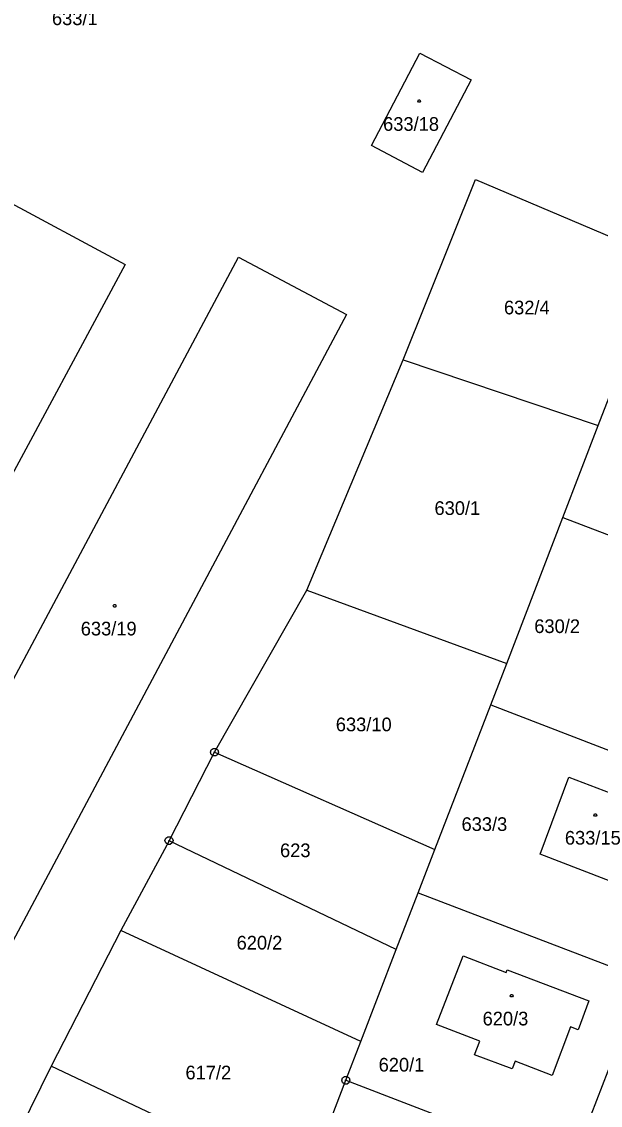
# Model space of a CAD drawing. Extents: x -759060 to -757386, y -1172273 to -1170948.
# Drawn here: x -758247.7 to -758175.7, y -1171430.9 to -1171296.1 of the extents above; entities that cross this region are included whole.
import ezdxf

# ---------------------------------------------------------------- set-up
doc = ezdxf.new("R2010")
doc.units = 0
for name, color, linetype in [('Vrstva 1', 7, 'Continuous'), ('Vrstva 12', 7, 'Continuous'), ('Vrstva 2', 7, 'Continuous'), ('Vrstva 5', 7, 'Continuous'), ('Vrstva 8', 7, 'Continuous')]:
    doc.layers.add(name, color=color, linetype=linetype)

msp = doc.modelspace()

# ---------------------------------------------------------------- linework, layer by layer
at = {"layer": 'Vrstva 1'}
for p, q in [((-758204.21, -1171311.5), (-758198.17, -1171299.99)), ((-758198.17, -1171299.99), (-758191.81, -1171303.33)), ((-758191.81, -1171303.33), (-758197.86, -1171314.86)), ((-758267.3, -1171308.84), (-758234.85, -1171326.27)), ((-758197.86, -1171314.86), (-758204.21, -1171311.5)), ((-758200.25, -1171338.13), (-758191.24, -1171315.72)), ((-758191.24, -1171315.72), (-758168.03, -1171325.59)), ((-758263.01, -1171404.59), (-758220.74, -1171325.36)), ((-758220.74, -1171325.36), (-758207.32, -1171332.5)), ((-758234.85, -1171326.27), (-758257.96, -1171369.23)), ((-758207.32, -1171332.5), (-758249.54, -1171411.77)), ((-758175.99, -1171346.32), (-758171.41, -1171334.41)), ((-758212.25, -1171366.8), (-758200.25, -1171338.13)), ((-758200.25, -1171338.13), (-758175.99, -1171346.32)), ((-758180.38, -1171357.75), (-758175.99, -1171346.32)), ((-758187.37, -1171375.93), (-758180.38, -1171357.75)), ((-758180.38, -1171357.75), (-758152.42, -1171368.5)), ((-758223.72, -1171386.96), (-758212.25, -1171366.8)), ((-758212.25, -1171366.8), (-758187.37, -1171375.93)), ((-758189.35, -1171381.08), (-758187.37, -1171375.93)), ((-758196.3, -1171399.06), (-758189.35, -1171381.08)), ((-758189.35, -1171381.08), (-758161.39, -1171391.83)), ((-758229.38, -1171397.96), (-758223.72, -1171386.96)), ((-758223.72, -1171386.96), (-758196.3, -1171399.06)), ((-758183.23, -1171399.64), (-758179.64, -1171390.04)), ((-758179.64, -1171390.04), (-758168.69, -1171394.27)), ((-758229.38, -1171397.96), (-758235.4, -1171409.14)), ((-758201.11, -1171411.49), (-758229.38, -1171397.96)), ((-758198.38, -1171404.43), (-758196.3, -1171399.06)), ((-758172.46, -1171403.81), (-758183.23, -1171399.64)), ((-758201.11, -1171411.49), (-758198.38, -1171404.43)), ((-758198.38, -1171404.43), (-758170.38, -1171415.15)), ((-758235.4, -1171409.14), (-758244.03, -1171426.01)), ((-758205.53, -1171422.96), (-758235.4, -1171409.14)), ((-758205.53, -1171422.96), (-758201.11, -1171411.49)), ((-758196.09, -1171420.83), (-758192.8, -1171412.3)), ((-758192.8, -1171412.3), (-758187.44, -1171414.37)), ((-758187.44, -1171414.37), (-758187.31, -1171414.03)), ((-758187.31, -1171414.03), (-758177.15, -1171417.9)), ((-758170.38, -1171415.15), (-758179.37, -1171438.48)), ((-758177.15, -1171417.9), (-758178.48, -1171421.47)), ((-758190.71, -1171422.89), (-758196.09, -1171420.83)), ((-758179.42, -1171421.11), (-758181.73, -1171427.19)), ((-758178.48, -1171421.47), (-758179.42, -1171421.11)), ((-758207.39, -1171427.77), (-758205.53, -1171422.96)), ((-758191.36, -1171424.58), (-758190.71, -1171422.89)), ((-758186.71, -1171426.34), (-758191.36, -1171424.58)), ((-758186.34, -1171425.38), (-758186.71, -1171426.34)), ((-758181.73, -1171427.19), (-758186.34, -1171425.38)), ((-758244.03, -1171426.01), (-758252.61, -1171443.29)), ((-758212.47, -1171440.95), (-758244.03, -1171426.01)), ((-758212.47, -1171440.95), (-758207.39, -1171427.77)), ((-758207.39, -1171427.77), (-758179.37, -1171438.48))]:
    msp.add_line(p, q, dxfattribs=at)
at = {"layer": 'Vrstva 12'}
for p, q in [((-758204.21, -1171311.5), (-758198.17, -1171299.99)), ((-758198.17, -1171299.99), (-758191.81, -1171303.33)), ((-758191.81, -1171303.33), (-758197.86, -1171314.86)), ((-758267.3, -1171308.84), (-758234.85, -1171326.27)), ((-758197.86, -1171314.86), (-758204.21, -1171311.5)), ((-758263.01, -1171404.59), (-758220.74, -1171325.36)), ((-758220.74, -1171325.36), (-758207.32, -1171332.5)), ((-758234.85, -1171326.27), (-758257.96, -1171369.23)), ((-758207.32, -1171332.5), (-758249.54, -1171411.77)), ((-758183.23, -1171399.64), (-758179.64, -1171390.04)), ((-758179.64, -1171390.04), (-758168.69, -1171394.27)), ((-758172.46, -1171403.81), (-758183.23, -1171399.64)), ((-758196.09, -1171420.83), (-758192.8, -1171412.3)), ((-758192.8, -1171412.3), (-758187.44, -1171414.37)), ((-758187.44, -1171414.37), (-758187.31, -1171414.03)), ((-758187.31, -1171414.03), (-758177.15, -1171417.9)), ((-758177.15, -1171417.9), (-758178.48, -1171421.47)), ((-758190.71, -1171422.89), (-758196.09, -1171420.83)), ((-758179.42, -1171421.11), (-758181.73, -1171427.19)), ((-758178.48, -1171421.47), (-758179.42, -1171421.11)), ((-758191.36, -1171424.58), (-758190.71, -1171422.89)), ((-758186.71, -1171426.34), (-758191.36, -1171424.58)), ((-758186.34, -1171425.38), (-758186.71, -1171426.34)), ((-758181.73, -1171427.19), (-758186.34, -1171425.38))]:
    msp.add_line(p, q, dxfattribs=at)
at = {"layer": 'Vrstva 5'}
for points in [[(-758198.17, -1171305.8), (-758198.08, -1171305.95), (-758198.17, -1171306.1), (-758198.35, -1171306.1), (-758198.44, -1171305.95), (-758198.35, -1171305.8)], [(-758236.07, -1171368.6), (-758235.98, -1171368.75), (-758236.07, -1171368.9), (-758236.25, -1171368.9), (-758236.34, -1171368.75), (-758236.25, -1171368.6)], [(-758176.26, -1171394.62), (-758176.17, -1171394.77), (-758176.26, -1171394.92), (-758176.44, -1171394.92), (-758176.53, -1171394.77), (-758176.44, -1171394.62)], [(-758186.67, -1171417.09), (-758186.58, -1171417.24), (-758186.67, -1171417.39), (-758186.85, -1171417.39), (-758186.94, -1171417.24), (-758186.85, -1171417.09)]]:
    msp.add_lwpolyline(points, close=True, dxfattribs=at)
at = {"layer": 'Vrstva 8'}
for p, q in [((-758223.84, -1171386.96), (-758223.6, -1171386.96)), ((-758229.5, -1171397.96), (-758229.26, -1171397.96)), ((-758207.51, -1171427.77), (-758207.27, -1171427.77))]:
    msp.add_line(p, q, dxfattribs=at)
for points in [[(-758223.57, -1171386.48), (-758223.32, -1171386.66), (-758223.22, -1171386.95), (-758223.32, -1171387.24), (-758223.57, -1171387.42), (-758223.88, -1171387.42), (-758224.13, -1171387.24), (-758224.23, -1171386.95), (-758224.13, -1171386.66), (-758223.88, -1171386.48)], [(-758229.23, -1171397.48), (-758228.98, -1171397.66), (-758228.88, -1171397.95), (-758228.98, -1171398.24), (-758229.23, -1171398.42), (-758229.54, -1171398.42), (-758229.79, -1171398.24), (-758229.89, -1171397.95), (-758229.79, -1171397.66), (-758229.54, -1171397.48)], [(-758207.24, -1171427.29), (-758206.99, -1171427.47), (-758206.89, -1171427.76), (-758206.99, -1171428.05), (-758207.24, -1171428.23), (-758207.55, -1171428.23), (-758207.8, -1171428.05), (-758207.9, -1171427.76), (-758207.8, -1171427.47), (-758207.55, -1171427.29)]]:
    msp.add_lwpolyline(points, close=True, dxfattribs=at)

# ---------------------------------------------------------------- texts
at = {"layer": 'Vrstva 2'}
for s, p in [('633/1', (-758243.949, -1171296.51)), ('633/18', (-758202.749, -1171309.66)), ('632/4', (-758187.714, -1171332.49)), ('630/1', (-758196.359, -1171357.44)), ('630/2', (-758183.941, -1171372.13)), ('633/19', (-758240.368, -1171372.43)), ('633/10', (-758208.635, -1171384.35)), ('633/3', (-758192.994, -1171396.75)), ('633/15', (-758180.135, -1171398.45)), ('623', (-758215.575, -1171400.01)), ('620/2', (-758220.977, -1171411.5)), ('620/3', (-758190.371, -1171420.94)), ('620/1', (-758203.306, -1171426.68)), ('617/2', (-758227.339, -1171427.65))]:
    msp.add_text(s, height=1.7, dxfattribs=at).set_placement(p)

doc.saveas('drawing.dxf')
